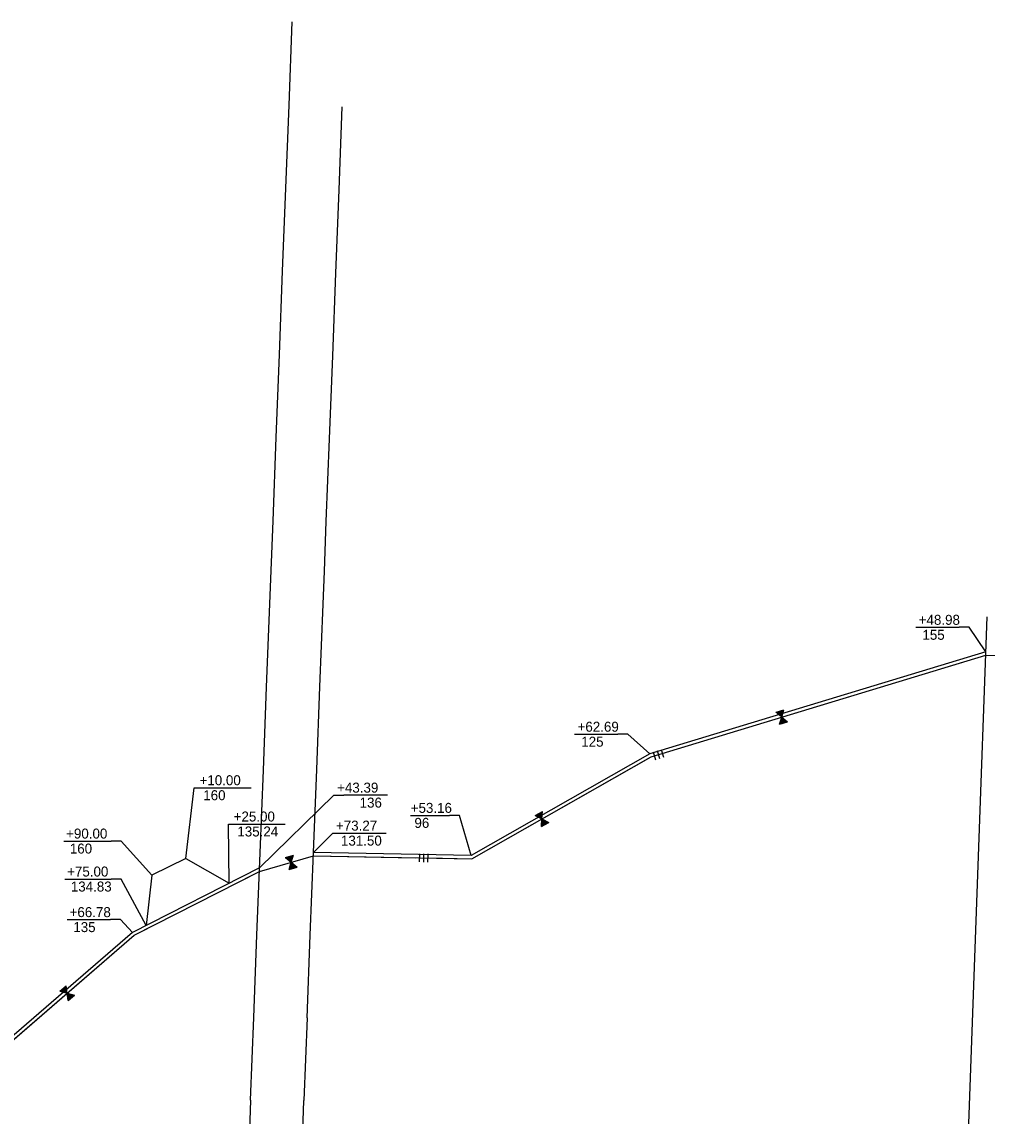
# Model space of a CAD drawing. Extents: x 979729 to 993523, y 1834148 to 1845433.
# Drawn here: x 991076 to 991656, y 1839507 to 1840165 of the extents above; entities that cross this region are included whole.
import ezdxf

# ---------------------------------------------------------------- set-up
doc = ezdxf.new("R2010")
doc.units = 0
for name, color, linetype in [('42', 7, 'Continuous'), ('51', 7, 'Continuous'), ('53', 7, 'Continuous'), ('R_Draft', 7, 'Continuous'), ('S_EXIST_ROW', 7, 'Continuous')]:
    doc.layers.add(name, color=color, linetype=linetype)

msp = doc.modelspace()

# ---------------------------------------------------------------- linework, layer by layer
at = {"layer": '42'}
for p, q in [((991453.92, 1839723.26), (991654.91, 1839784.25)), ((991654.91, 1839784.25), (991704.92, 1839783.66)), ((991528.96, 1839749.94), (991532.44, 1839747.08)), ((991529.03, 1839749.91), (991529.04, 1839749.97)), ((991529.24, 1839749.76), (991529.33, 1839750.06)), ((991529.44, 1839749.57), (991529.62, 1839750.15)), ((991529.66, 1839749.41), (991529.91, 1839750.23)), ((991529.86, 1839749.22), (991530.19, 1839750.32)), ((991530.07, 1839749.03), (991530.48, 1839750.41)), ((991530.28, 1839748.88), (991530.77, 1839750.5)), ((991530.51, 1839748.79), (991531.01, 1839750.42)), ((991530.71, 1839748.56), (991531.34, 1839750.67)), ((991530.92, 1839748.41), (991531.63, 1839750.76)), ((991531.12, 1839748.19), (991531.92, 1839750.84)), ((991531.34, 1839748.07), (991532.21, 1839750.93)), ((991531.54, 1839747.85), (991532.49, 1839751.02)), ((991531.75, 1839747.7), (991532.78, 1839751.11)), ((991531.95, 1839747.5), (991533.07, 1839751.19)), ((991532.18, 1839747.38), (991533.36, 1839751.28)), ((991532.37, 1839747.16), (991533.64, 1839751.37)), ((991532.44, 1839747.08), (991533.74, 1839751.4)), ((991531.13, 1839742.77), (991532.44, 1839747.08)), ((991531.17, 1839742.84), (991531.22, 1839742.8)), ((991531.27, 1839743.08), (991531.51, 1839742.88)), ((991531.33, 1839743.36), (991531.8, 1839742.97)), ((991531.42, 1839743.6), (991532.09, 1839743.06)), ((991531.49, 1839743.87), (991532.37, 1839743.14)), ((991531.55, 1839744.14), (991532.66, 1839743.23)), ((991531.64, 1839744.39), (991532.95, 1839743.32)), ((991531.79, 1839744.6), (991533.11, 1839743.51)), ((991531.82, 1839744.89), (991533.52, 1839743.49)), ((991531.92, 1839745.14), (991533.81, 1839743.58)), ((991531.96, 1839745.43), (991534.1, 1839743.67)), ((991532.07, 1839745.66), (991534.39, 1839743.76)), ((991532.11, 1839745.95), (991534.67, 1839743.84)), ((991532.21, 1839746.19), (991534.96, 1839743.93)), ((991532.27, 1839746.46), (991535.25, 1839744.02)), ((991532.39, 1839746.69), (991535.53, 1839744.1)), ((991532.43, 1839746.98), (991535.82, 1839744.19)), ((991532.44, 1839747.08), (991535.92, 1839744.22)), ((991346.36, 1839661.92), (991453.92, 1839723.26)), ((991455.16, 1839726.24), (991456.61, 1839721.46)), ((991457.55, 1839726.97), (991459, 1839722.18)), ((991459.94, 1839727.69), (991461.39, 1839722.91)), ((991387.33, 1839686.43), (991387.56, 1839689.73)), ((991387.58, 1839686.33), (991387.82, 1839689.88)), ((991387.82, 1839686.18), (991388.09, 1839690.03)), ((991388.06, 1839686.11), (991388.35, 1839690.18)), ((991388.3, 1839685.94), (991388.61, 1839690.33)), ((991388.38, 1839685.88), (991388.69, 1839690.38)), ((991384.35, 1839687.9), (991388.38, 1839685.88)), ((991384.43, 1839687.88), (991384.43, 1839687.94)), ((991384.67, 1839687.78), (991384.69, 1839688.09)), ((991384.91, 1839687.64), (991384.95, 1839688.24)), ((991385.16, 1839687.54), (991385.22, 1839688.39)), ((991385.4, 1839687.39), (991385.48, 1839688.54)), ((991385.64, 1839687.25), (991385.74, 1839688.69)), ((991385.88, 1839687.15), (991386, 1839688.84)), ((991386.13, 1839687.12), (991386.25, 1839688.82)), ((991386.37, 1839686.94), (991386.52, 1839689.14)), ((991386.61, 1839686.84), (991386.78, 1839689.28)), ((991386.85, 1839686.67), (991387.04, 1839689.43)), ((991387.09, 1839686.6), (991387.3, 1839689.58)), ((991388.07, 1839681.38), (991388.38, 1839685.88)), ((991388.2, 1839683.08), (991389.71, 1839682.32)), ((991388.27, 1839683.61), (991390.24, 1839682.62)), ((991388.28, 1839684.16), (991390.76, 1839682.92)), ((991388.3, 1839683.87), (991390.5, 1839682.77)), ((991388.3, 1839683.31), (991389.83, 1839682.55)), ((991388.32, 1839684.7), (991391.28, 1839683.22)), ((991388.34, 1839684.41), (991391.02, 1839683.07)), ((991388.35, 1839685.24), (991391.8, 1839683.51)), ((991388.35, 1839684.96), (991391.54, 1839683.36)), ((991388.38, 1839685.88), (991392.41, 1839683.86)), ((991388.39, 1839685.78), (991392.32, 1839683.81)), ((991388.42, 1839685.49), (991392.06, 1839683.66)), ((991388.09, 1839681.46), (991388.15, 1839681.43)), ((991388.13, 1839682), (991388.67, 1839681.73)), ((991388.13, 1839681.72), (991388.41, 1839681.58)), ((991388.16, 1839682.54), (991389.19, 1839682.02)), ((991388.16, 1839682.26), (991388.93, 1839681.88)), ((991388.17, 1839682.82), (991389.45, 1839682.17)), ((991218.7, 1839654.28), (991251.09, 1839663.8)), ((991235.67, 1839661.71), (991236.18, 1839663.33)), ((991236.1, 1839661.39), (991236.75, 1839663.5)), ((991236.31, 1839661.24), (991237.04, 1839663.58)), ((991236.5, 1839661.02), (991237.33, 1839663.67)), ((991236.73, 1839660.89), (991237.62, 1839663.75)), ((991236.92, 1839660.67), (991237.91, 1839663.84)), ((991237.13, 1839660.52), (991238.19, 1839663.92)), ((991237.34, 1839660.32), (991238.48, 1839664)), ((991237.56, 1839660.2), (991238.77, 1839664.09)), ((991237.75, 1839659.98), (991239.06, 1839664.17)), ((991237.81, 1839659.9), (991239.15, 1839664.2)), ((991251.09, 1839663.8), (991346.36, 1839661.92)), ((991314.79, 1839665.04), (991314.69, 1839660.04)), ((991317.29, 1839664.99), (991317.19, 1839660)), ((991319.79, 1839664.94), (991319.69, 1839659.95)), ((991234.36, 1839662.79), (991237.81, 1839659.9)), ((991234.43, 1839662.76), (991234.45, 1839662.82)), ((991234.64, 1839662.6), (991234.73, 1839662.9)), ((991234.84, 1839662.41), (991235.02, 1839662.99)), ((991235.06, 1839662.25), (991235.31, 1839663.07)), ((991235.26, 1839662.06), (991235.6, 1839663.16)), ((991235.46, 1839661.87), (991235.89, 1839663.24)), ((991235.91, 1839661.62), (991236.41, 1839663.25)), ((991236.47, 1839655.6), (991237.81, 1839659.9)), ((991236.9, 1839656.97), (991238, 1839656.05)), ((991237, 1839657.22), (991238.29, 1839656.13)), ((991237.14, 1839657.42), (991238.45, 1839656.32)), ((991237.18, 1839657.71), (991238.87, 1839656.3)), ((991237.28, 1839657.96), (991239.16, 1839656.39)), ((991237.32, 1839658.25), (991239.45, 1839656.47)), ((991237.44, 1839658.48), (991239.73, 1839656.56)), ((991237.48, 1839658.77), (991240.02, 1839656.64)), ((991237.58, 1839659.01), (991240.31, 1839656.72)), ((991237.64, 1839659.28), (991240.6, 1839656.81)), ((991237.76, 1839659.51), (991240.89, 1839656.89)), ((991237.8, 1839659.8), (991241.17, 1839656.98)), ((991237.81, 1839659.9), (991241.27, 1839657.01)), ((991143.55, 1839616.09), (991218.7, 1839654.28)), ((991236.51, 1839655.67), (991236.56, 1839655.62)), ((991236.61, 1839655.91), (991236.85, 1839655.71)), ((991236.67, 1839656.18), (991237.14, 1839655.79)), ((991236.77, 1839656.43), (991237.43, 1839655.88)), ((991236.83, 1839656.7), (991237.72, 1839655.96)), ((991057.83, 1839542.04), (991143.55, 1839616.09)), ((991101.58, 1839581.74), (991101.23, 1839584.49)), ((991101.83, 1839581.71), (991101.46, 1839584.68)), ((991102.1, 1839581.59), (991101.69, 1839584.88)), ((991102.36, 1839581.54), (991101.91, 1839585.08)), ((991102.62, 1839581.45), (991102.14, 1839585.27)), ((991102.87, 1839581.42), (991102.37, 1839585.47)), ((991103.14, 1839581.3), (991102.6, 1839585.66)), ((991103.23, 1839581.26), (991102.67, 1839585.73)), ((991098.89, 1839582.46), (991103.23, 1839581.26)), ((991098.97, 1839582.46), (991098.96, 1839582.52)), ((991099.23, 1839582.41), (991099.19, 1839582.72)), ((991099.49, 1839582.31), (991099.41, 1839582.91)), ((991099.75, 1839582.26), (991099.64, 1839583.11)), ((991100.01, 1839582.17), (991099.87, 1839583.31)), ((991100.27, 1839582.08), (991100.1, 1839583.5)), ((991100.53, 1839582.02), (991100.32, 1839583.7)), ((991100.78, 1839582.04), (991100.57, 1839583.73)), ((991101.05, 1839581.91), (991100.78, 1839584.09)), ((991101.31, 1839581.86), (991101.01, 1839584.29)), ((991103.23, 1839581.26), (991107.57, 1839580.05)), ((991103.79, 1839576.79), (991103.23, 1839581.26)), ((991103.26, 1839581.16), (991107.5, 1839579.99)), ((991103.33, 1839580.62), (991107.04, 1839579.6)), ((991103.34, 1839580.88), (991107.27, 1839579.79)), ((991103.38, 1839580.35), (991106.82, 1839579.4)), ((991103.4, 1839580.09), (991106.59, 1839579.2)), ((991103.46, 1839579.55), (991106.14, 1839578.81)), ((991103.48, 1839579.81), (991106.36, 1839579.01)), ((991103.54, 1839579.27), (991105.91, 1839578.61)), ((991103.56, 1839579.01), (991105.68, 1839578.42)), ((991103.6, 1839578.48), (991105.23, 1839578.02)), ((991103.61, 1839578.21), (991105, 1839577.83)), ((991103.65, 1839578.72), (991105.29, 1839578.27)), ((991103.66, 1839577.94), (991104.77, 1839577.63)), ((991103.72, 1839577.66), (991104.54, 1839577.44)), ((991103.73, 1839577.4), (991104.32, 1839577.24)), ((991103.79, 1839577.13), (991104.09, 1839577.04)), ((991103.8, 1839576.86), (991103.86, 1839576.85))]:
    msp.add_line(p, q, dxfattribs=at)
for points in [[(991628.58, 1839776.26), (991654.91, 1839784.25), (991704.92, 1839783.66), (991759.13, 1839789.22)], [(991460.67, 1839725.3), (991573.92, 1839759.67)], [(991528.96, 1839749.94), (991533.74, 1839751.4)], [(991531.13, 1839742.77), (991535.92, 1839744.22)], [(991319.74, 1839662.45), (991346.36, 1839661.92), (991453.53, 1839723.03)], [(991384.35, 1839687.9), (991388.69, 1839690.38)], [(991388.07, 1839681.38), (991392.41, 1839683.86)], [(991201.3, 1839645.44), (991218.7, 1839654.28), (991251.09, 1839663.8), (991312.24, 1839662.59)], [(991234.36, 1839662.79), (991239.15, 1839664.2)], [(991236.47, 1839655.6), (991241.27, 1839657.01)], [(991049.92, 1839529.29), (991057.83, 1839542.04), (991143.55, 1839616.09), (991151.55, 1839620.15)], [(991098.89, 1839582.46), (991102.67, 1839585.73)], [(991103.79, 1839576.79), (991107.57, 1839580.05)]]:
    msp.add_lwpolyline(points, dxfattribs=at)
at = {"layer": '51'}
for points in [[(991654.98, 1839786.36), (991453.13, 1839725.1)], [(991453.13, 1839725.1), (991345.85, 1839663.93), (991251.17, 1839665.8)], [(991218.79, 1839656.57), (991142.43, 1839617.76), (991056.3, 1839543.35)]]:
    msp.add_lwpolyline(points, dxfattribs=at)
at = {"layer": '53'}
for p, q in [((991174.46, 1839662.24), (991154.07, 1839652.06)), ((991174.46, 1839662.24), (991200.44, 1839647.24)), ((991154.07, 1839652.06), (991150.62, 1839621.92))]:
    msp.add_line(p, q, dxfattribs=at)
at = {"layer": 'R_Draft'}
for p, q in [((991612.89, 1839801), (991638.93, 1839801)), ((991408, 1839736.78), (991434.04, 1839736.78)), ((991185.56, 1839704.65), (991213.66, 1839704.65)), ((991295.52, 1839700.22), (991269.48, 1839700.22)), ((991309.34, 1839688.04), (991332.91, 1839688.04)), ((991206.05, 1839682.86), (991234.15, 1839682.86)), ((991268.75, 1839677.39), (991294.79, 1839677.39)), ((991101.14, 1839672.61), (991129.74, 1839672.61)), ((991101.75, 1839649.81), (991129.74, 1839649.81)), ((991103.23, 1839625.43), (991129.27, 1839625.43))]:
    msp.add_line(p, q, dxfattribs=at)
for points in [[(991654.98, 1839786.36), (991644.93, 1839801), (991638.93, 1839801)], [(991453.13, 1839725.1), (991440.04, 1839736.78), (991434.04, 1839736.78)], [(991174.46, 1839662.24), (991179.56, 1839704.65), (991185.56, 1839704.65)], [(991218.79, 1839656.57), (991263.48, 1839700.22), (991269.48, 1839700.22)], [(991345.85, 1839663.93), (991338.91, 1839688.04), (991332.91, 1839688.04)], [(991200.44, 1839647.24), (991200.05, 1839682.86), (991206.05, 1839682.86)], [(991251.17, 1839665.8), (991262.75, 1839677.39), (991268.75, 1839677.39)], [(991154.07, 1839652.06), (991135.74, 1839672.61), (991129.74, 1839672.61)], [(991150.62, 1839621.92), (991135.74, 1839649.81), (991129.74, 1839649.81)], [(991142.43, 1839617.76), (991135.27, 1839625.43), (991129.27, 1839625.43)]]:
    msp.add_lwpolyline(points, dxfattribs=at)
at = {"layer": 'S_EXIST_ROW'}
for p, q in [((991236.5, 1840114.69), (991238.43, 1840164.63)), ((991234.57, 1840064.75), (991236.5, 1840114.69)), ((991266.55, 1840063.66), (991268.48, 1840113.62)), ((991232.64, 1840014.82), (991234.57, 1840064.75)), ((991264.62, 1840013.7), (991266.55, 1840063.66)), ((991230.71, 1839964.88), (991232.64, 1840014.82)), ((991262.7, 1839964), (991264.62, 1840013.7)), ((991228.78, 1839914.94), (991230.71, 1839964.88)), ((991260.78, 1839914.3), (991262.7, 1839964)), ((991226.85, 1839865), (991228.78, 1839914.94)), ((991258.85, 1839864.6), (991260.78, 1839914.3)), ((991224.92, 1839815.06), (991226.85, 1839865)), ((991257.7, 1839834.62), (991258.85, 1839864.6)), ((991256.93, 1839814.9), (991257.7, 1839834.62)), ((991222.99, 1839765.13), (991224.92, 1839815.06)), ((991255.01, 1839765.2), (991256.93, 1839814.9)), ((991653.95, 1839757.53), (991655.74, 1839807.35)), ((991221.05, 1839715.19), (991222.99, 1839765.13)), ((991253.09, 1839715.5), (991255.01, 1839765.2)), ((991652.16, 1839707.71), (991653.95, 1839757.53)), ((991219.14, 1839665.64), (991221.05, 1839715.19)), ((991251.17, 1839665.8), (991253.09, 1839715.5)), ((991650.36, 1839657.9), (991652.16, 1839707.71)), ((991217.22, 1839616.1), (991219.14, 1839665.64)), ((991249.25, 1839616.1), (991251.17, 1839665.8)), ((991648.57, 1839608.08), (991650.36, 1839657.9)), ((991215.31, 1839566.56), (991217.22, 1839616.1)), ((991247.33, 1839566.41), (991249.25, 1839616.1)), ((991646.78, 1839558.26), (991648.57, 1839608.08)), ((991213.39, 1839517.01), (991215.31, 1839566.56)), ((991247.33, 1839566.41), (991245.4, 1839516.71)), ((991644.99, 1839508.44), (991646.78, 1839558.26)), ((991213.39, 1839517.01), (991211.48, 1839467.47)), ((991243.48, 1839467.01), (991245.4, 1839516.71)), ((991643.19, 1839458.63), (991644.99, 1839508.44))]:
    msp.add_line(p, q, dxfattribs=at)

# ---------------------------------------------------------------- texts
at = {"layer": 'R_Draft'}
for s, rotation, p in [('+48.98', 360, (991614.66, 1839802.5)), (' 155', 360, (991614.66, 1839793.5)), ('+62.69', 360, (991409.77, 1839738.28)), (' 125', 360, (991409.77, 1839729.28)), ('+10.00', 360, (991182.73, 1839706.15)), (' 160', 360, (991182.73, 1839697.15)), ('+43.39', 0, (991265.35, 1839701.72)), (' 136', 0, (991276.64, 1839692.72)), ('+25.00', 360, (991203.22, 1839684.36)), ('+53.16', 360, (991309.56, 1839689.54)), ('+73.27', 0, (991264.67, 1839678.89)), (' 96', 360, (991309.56, 1839680.54)), ('+90.00', 360, (991102.59, 1839674.11)), (' 135.24', 360, (991203.22, 1839675.36)), (' 160', 360, (991102.59, 1839665.11)), (' 131.50', 0, (991265.43, 1839669.89)), ('+75.00', 360, (991103.2, 1839651.31)), (' 134.83', 360, (991103.2, 1839642.31)), ('+66.78', 360, (991104.68, 1839626.93)), (' 135', 360, (991104.68, 1839617.93))]:
    msp.add_text(s, height=6, rotation=rotation, dxfattribs=at).set_placement(p)

doc.saveas('drawing.dxf')
